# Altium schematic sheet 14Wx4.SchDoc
size A2; SheetNumber: 0; SheetTotal: 0; PageSetup: Record=PageOptions|CenterHorizontal=True|CenterVertical=True|PrintScale=0.50|XCorrection=1.00|YCorrection=1.00|PrintKind=0|BorderSize=5000000|LeftOffset=0|BottomOffset=0|Orientation=2|PaperLength=1000|PaperWidth=1000|Scale=100|PaperSource=7|PrintQuality=-4|MediaType=1|DitherType=10|PaperKind=A4|PrintScaleMode=1
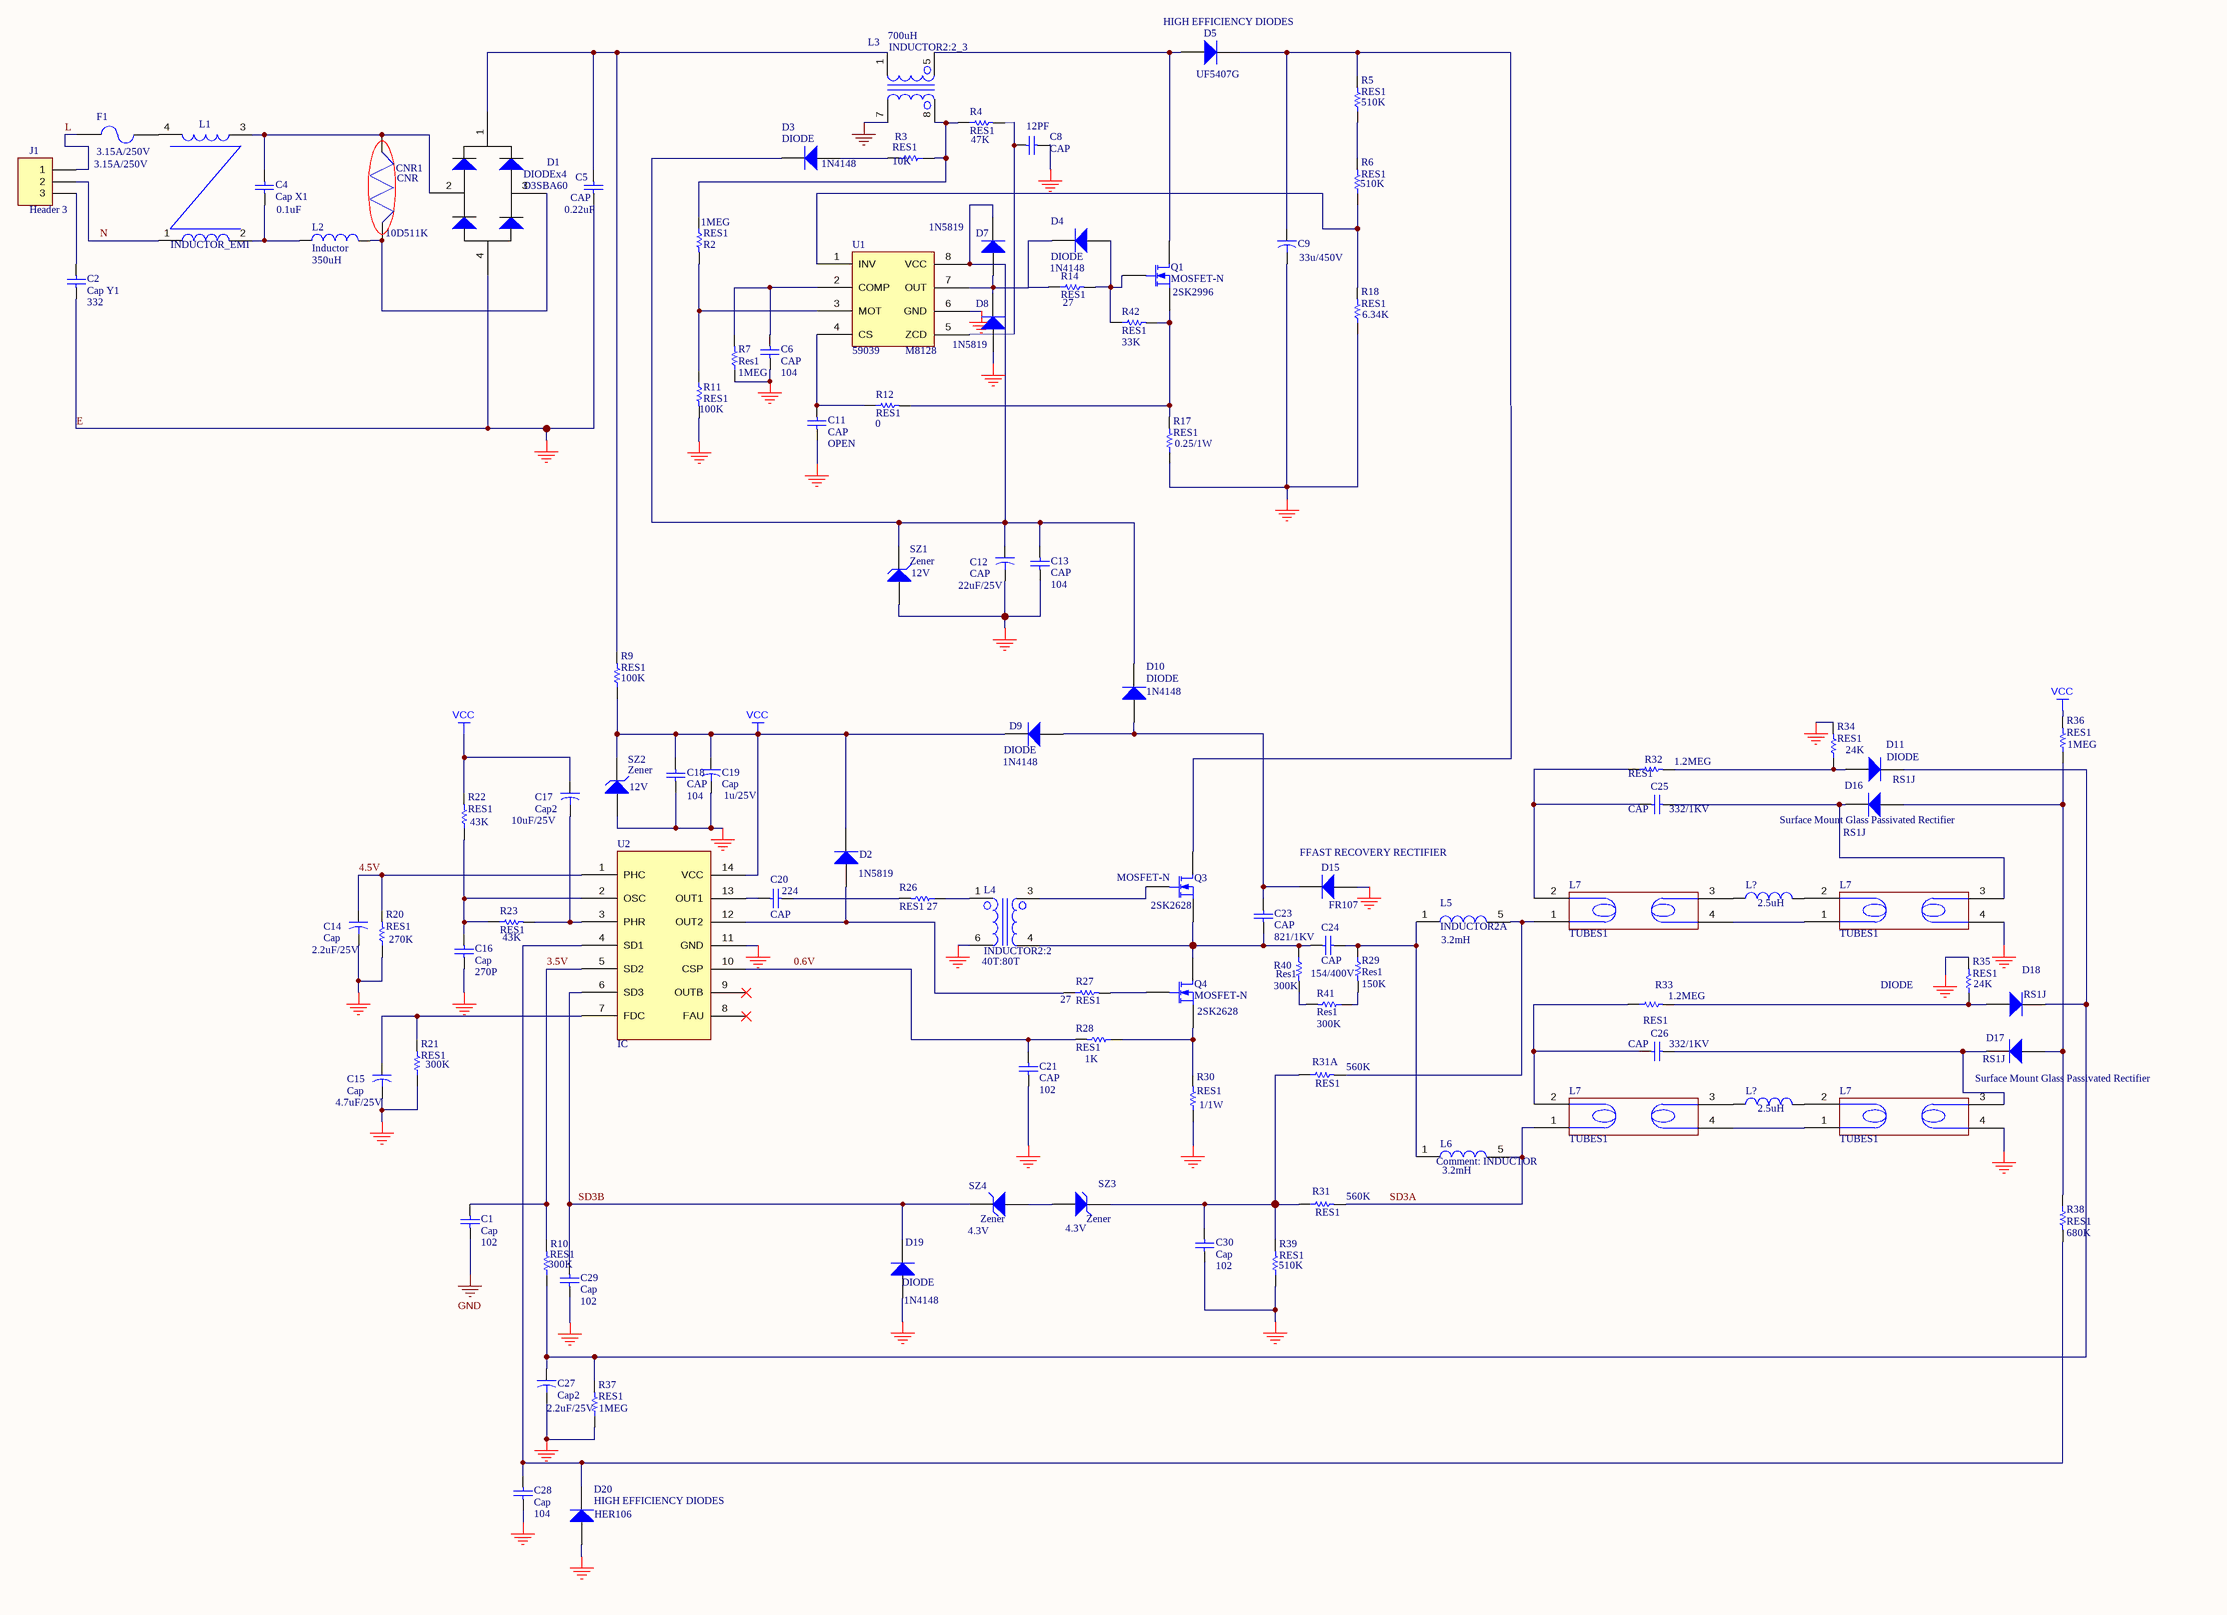
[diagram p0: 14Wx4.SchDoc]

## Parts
(Parts that share a designator on the sheet are numbered #1, #2 ... from top to bottom, then left to right.)
C1  Cap  value 102  [C0805A]
C2  Cap Y1  value 332  [RAD-0.3]
C4  Cap X1  value 0.1uF  [RAD0.6B]
C5  CAP  value 0.22uF  [RAD0.6B]
C6  CAP  value 104  [RAD0.2B]
C8  CAP  value 12PF  [C0805A]
C9  value 33u/450V  [RB.3/.6A]  (hidden comment: Cap2)
C11  CAP  value OPEN  [C0805A]
C12  CAP  value 22uF/25V  [RB.2/.2]
C13  CAP  value 104  [RAD0.2B]
C14  Cap  value 2.2uF/25V  [RB.2/.2]
C15  Cap  value 4.7uF/25V  [RB.2/.2]
C16  Cap  value 270P  [C0805A]
C17  Cap2  value 10uF/25V  [RB.2/.2]
C18  CAP  value 104  [RAD0.2B]
C19  Cap  value 1u/25V  [RB.2/.2]
C20  CAP  value 224  [C0805A]
C21  CAP  value 102  [C0805A]
C23  CAP  value 821/1KV  [RAD-0.3]
C24  CAP  value 154/400V  [RAD0.6A]
C25  CAP  value 332/1KV  [RAD0.6A]
C26  CAP  value 332/1KV  [RAD0.6A]
C27  Cap2  value 2.2uF/25V  [RB.2/.2]
C28  Cap  value 104  [C0805A]
C29  Cap  value 102  [C0805A]
C30  Cap  value 102  [C0805A]
CNR1  CNR  value 10D511K  [RAD-0.2]
D1  DIODEx4  value D3SBA60  [SIP4B]
D2  value 1N5819  [DO-41]  (hidden comment: Diode 1N5819)
D3  DIODE  value 1N4148  [CD3216-1206A]
D4  DIODE  value 1N4148  [CD3216-1206A]
D5  HIGH EFFICIENCY DIODES  value UF5407G  [DIODE0.7A]
D7  value 1N5819  [DO-41]  (hidden comment: Diode 1N5819)
D8  value 1N5819  [DO-41]  (hidden comment: Diode 1N5819)
D9  DIODE  value 1N4148  [CD3216-1206A]
D10  DIODE  value 1N4148  [CD3216-1206A]
D11  DIODE  value RS1J  [CD4532-1810]
D15  FFAST RECOVERY RECTIFIER  value FR107  [DIODE-0.4]
D16  Surface Mount Glass Passivated Rectifier  value RS1J  [CD4532-1810]
D17  Surface Mount Glass Passivated Rectifier  value RS1J  [CD4532-1810]
D18  DIODE  value RS1J  [CD4532-1810]
D19  DIODE  value 1N4148  [CD3216-1206A]
D20  HIGH EFFICIENCY DIODES  value HER106  [DIODE-0.4]
F1  3.15A/250V  [FUSE0.6]
J1  Header 3  [IDC6C]
L1  INDUCTOR_EMI  [EE1916H_EMI]
L2  Inductor  value 350uH  [Q.3/.3]
L3  INDUCTOR2:2_3  value 700uH  [EE25_PFC8]
L4  INDUCTOR2:2  value 40T:80T  [EE0808]
L5  INDUCTOR2A  value 3.2mH  [EE2520_LRES8]
L6  INDUCTOR  value 3.2mH  [EE2520_LRES8]
L7#1  TUBES1  [IDC14-MIN]
L7#2  TUBES1  [IDC14-MIN]
L7#3  TUBES1  [IDC14-MIN]
L7#4  TUBES1  [IDC14-MIN]
L?#1  value 2.5uH  [0402-A]  (hidden comment: Inductor)
L?#2  value 2.5uH  [0402-A]  (hidden comment: Inductor)
Q1  MOSFET-N  value 2SK2996  [TO-220B]
Q3  MOSFET-N  value 2SK2628  [TO-220B]
Q4  MOSFET-N  value 2SK2628  [TO-220B]
R2  RES1  value 1MEG  [2012[0805]A]
R3  RES1  value 10K  [2012[0805]A]
R4  RES1  value 47K  [2012[0805]A]
R5  RES1  value 510K  [2012[0805]A]
R6  RES1  value 510K  [2012[0805]A]
R7  Res1  value 1MEG  [2012[0805]A]
R9  RES1  value 100K  [2012[0805]A]
R10  RES1  value 300K  [2012[0805]A]
R11  RES1  value 100K  [2012[0805]A]
R12  RES1  value 0  [2012[0805]A]
R14  RES1  value 27  [2012[0805]A]
R17  RES1  value 0.25/1W  [AXIAL-0.5]
R18  RES1  value 6.34K  [2012[0805]A]
R20  RES1  value 270K  [2012[0805]A]
R21  RES1  value 300K  [2012[0805]A]
R22  RES1  value 43K  [2012[0805]A]
R23  RES1  value 43K  [2012[0805]A]
R26  RES1  value 27  [2012[0805]A]
R27  RES1  value 27  [2012[0805]A]
R28  RES1  value 1K  [2012[0805]A]
R29  Res1  value 150K  [2012[0805]A]
R30  RES1  value 1/1W  [AXIAL-0.5]
R31  RES1  value 560K  [2012[0805]A]
R31A  RES1  value 560K  [2012[0805]A]
R32  RES1  value 1.2MEG  [2012[0805]A]
R33  RES1  value 1.2MEG  [2012[0805]A]
R34  RES1  value 24K  [2012[0805]A]
R35  RES1  value 24K  [2012[0805]A]
R36  RES1  value 1MEG  [2012[0805]A]
R37  RES1  value 1MEG  [2012[0805]A]
R38  RES1  value 680K  [2012[0805]A]
R39  RES1  value 510K  [2012[0805]A]
R40  Res1  value 300K  [2012[0805]A]
R41  Res1  value 300K  [2012[0805]A]
R42  RES1  value 33K  [2012[0805]A]
SZ1  Zener  value 12V  [CD3216-1206A]
SZ2  Zener  value 12V  [CD3216-1206A]
SZ3  Zener  value 4.3V  [CD3216-1206A]
SZ4  Zener  value 4.3V  [CD3216-1206A]
U1  59039  value M8128  [DIP-8]
U2  IC

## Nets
E: C1.1 C2.1 C5.1 C6.1 C8.2 C9.2 C11.1 C12.2 C13.1 C14.2 C15.2 C16.1 C18.1 C19.2 C21.1 C27.2 C28.2 C29.1 C30.2 D1.4 D8.1(A) D15.1(A) D19.1(A) D20.1(A) L3.7 L4.6 L7#2.4(TR4) L7#4.4(TR4) R7.1 R11.2 R17.1 R18.1 R20.1 R21.1 R30.1 R34.2 R35.2 R37.1 R39.1 SZ1.1(A) SZ2.1(A) U1.6(GND) U2.11(GND)  [also labelled GND]
VCC: C17.1 C18.2 C19.1 D2.2(K) D9.2(K) R9.1 R22.2 R36.2 SZ2.2(K) U2.14(VCC)
0.6V: C21.2 R28.2 U2.10(CSP)
3.5V: C1.2 R10.2 U2.5(SD2)
4.5V: C14.1 R20.2 U2.1(PHC)
L: F1.1 J1.1
N: J1.2 L1.1(TR5)
SD3A: L6.5 L7#3.1(TR1) R31.2
SD3B: C29.2 D19.2(K) SZ4.2(K) U2.6(SD3)
NetC2_2: C2.2 J1.3
NetC4_1: C4.1 L1.2(TR6) L2.1
NetC5_2: C5.2 D1.1 L3.1 R9.2
NetC6_2: C6.2 R7.2 U1.2(COMP)
NetC8_1: C8.1 R4.2 U1.5(ZCD)
NetC9_1: C9.1 D5.2(K) Q3.1(D) R5.2
NetC11_2: C11.2 R12.1 U1.4(CS)
NetC12_1: C12.1 C13.2 D3.2(K) D7.2(K) D10.2(K) SZ1.2(K) U1.8(VCC)
NetC15_1: C15.1 R21.2 U2.7(FDC)
NetC16_2: C16.2 R22.1 R23.1 U2.2(OSC)
NetC17_2: C17.2 R23.2 U2.3(PHR)
NetC20_1: C20.1 R26.2
NetC20_2: C20.2 U2.13(OUT1)
NetC23_1: C23.1 C24.2 L4.4 Q3.3(S) Q4.1(D) R40.1
NetC23_2: C23.2 D9.1(A) D10.1(A) D15.2(K)
NetC24_1: C24.1 L5.1 L6.1 R29.1
NetC25_1: C25.1 L7#1.2(TR2) R32.1
NetC25_2: C25.2 D16.2(K) L7#2.3
NetC26_1: C26.1 D17.2(K) L7#4.3
NetC26_2: C26.2 L7#3.2(TR2) R33.1
NetC27_1: C27.1 D11.2(K) D18.2(K) R10.1 R37.2
NetC28_1: C28.1 D20.2(K) R38.2 U2.4(SD1)
NetC30_1: C30.1 R31.1 R31A.1 R39.2 SZ3.2(K)
NetCNR1_1: CNR1.1 D1.2 L1.3(TR5)
NetCNR1_2: CNR1.2 D1.3 L2.2
NetD2_1: D2.1(A) R27.1 U2.12(OUT2)
NetD3_1: D3.1(A) R3.2
NetD4_1: D4.1(A) Q1.2(G) R14.2 R42.1
NetD4_2: D4.2(K) D7.1(A) D8.2(K) U1.7(OUT)
NetD5_1: D5.1(A) L3.5 Q1.1(D)
NetD11_1: D11.1(A) R32.2 R34.1
NetD16_1: D16.1(A) D17.1(A) R36.1 R38.1
NetD18_1: D18.1(A) R33.2 R35.1
NetF1_2: F1.2 L1.4(TR6)
NetL3_8: L3.8 R2.1 R3.1 R4.1
NetL4_1: L4.1 R26.1
NetL4_3: L4.3 Q3.2(G)
NetL5_5: L5.5 L7#1.1(TR1) R31A.2
NetL7#1_3: L7#1.3 L?#1.1
NetL7#1_4: L7#1.4(TR4) L7#2.1(TR1)
NetL7#2_2: L7#2.2(TR2) L?#1.2
NetL7#3_3: L7#3.3 L?#2.1
NetL7#3_4: L7#3.4(TR4) L7#4.1(TR1)
NetL7#4_2: L7#4.2(TR2) L?#2.2
NetQ1_3: Q1.3(S) R12.2 R17.2 R42.2
NetQ4_2: Q4.2(G) R27.2
NetQ4_3: Q4.3(S) R28.1 R30.2
NetR2_2: R2.2 R11.1 U1.3(MOT)
NetR5_1: R5.1 R6.2
NetR6_1: R6.1 R18.2 U1.1(INV)
NetR29_2: R29.2 R41.1
NetR40_2: R40.2 R41.2
NetSZ3_1: SZ3.1(A) SZ4.1(A)

Not connected (* = marked no-connect by the designer): C4 2; R14 1; U2 8(FAU)* 9(OUTB)*

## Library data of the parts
C1 C16 C28-C30 = Cap: Ceramic Capacitor
C2 = CAP: Y Capacitor
C4 C5 = CAP: BOX Capacitor
C6 C13 C18 = CAP: MLCC Capacitor
C8 C11 C20 C21 = CAP: Ceramic Capacitor
C9 C12 C14 C15 C17 C19 C27 = Cap2: Electrolytic Capacitor
C23-C26 = CAP: POLYPROPYLENE FILM Capacitor
CNR1 = CNR: Varistor
D1 = DIODEx4: Bridge Diode
D2 D7 D8 = Diode 1N4007: 1 Amp General Purpose Rectifier
D3 D4 D9 D10 D19 = DIODE: Diode  75V,1A
D5 = DIODE: Diode HIGH EFFICIENCY RECTIFIERS 600V, 3A
D11 D15-D18 = DIODE: Diode FAST RECOVERY RECTIFIER 700V,1A
D20 = DIODE: Diode HIGH EFFICIENCY RECTIFIERS 600V, 1A
F1 = FUSE2: Fuse
J1 = Header 3: Jumper Wire Pin spacing 5mm         235-403(2LG+1G); VALUE: ºÝ¤l
L1 = INDUCTOR_EMI: EE19H Inductor; VALUE: 16mH
L2 = Inductor: Q Bobbin nductor; Code_IEC: 1005
L3 = INDUCTOR2:2_3: EE25 Inductor
L4 = INDUCTOR2:2: EE08 Inductor
L5 L6 = INDUCTOR2A: EE25 Inductor
L7#1-L7#4 = TUBES1: Jumper Wire Pin spacing 3.5mm    235-107/000-009; VALUE: LAMP
L?#1 L?#2 = Inductor: Code_IEC: 1005
Q1 = MOSFET-N: Transistor, MOSFET  600V, 11A; PackageDocument: 1995/1996
Q3 Q4 = MOSFET-N: Transistor, MOSFET  600V, 6A; PackageDocument: 1995/1996
R2-R6 R9-R12 R14 R18 R20-R23 R26-R28 R31 R31A R32-R39 R42 = RES1: Resistor 1/4W
R7 R29 R40 R41 = Res1: Resistor 1/4W
R17 R30 = RES1: Resistor 1W
SZ1-SZ4 = D Zener: Zener Diode 1/2W
U1 = 59039: IC, PFC Driver
U2 = M8145_1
